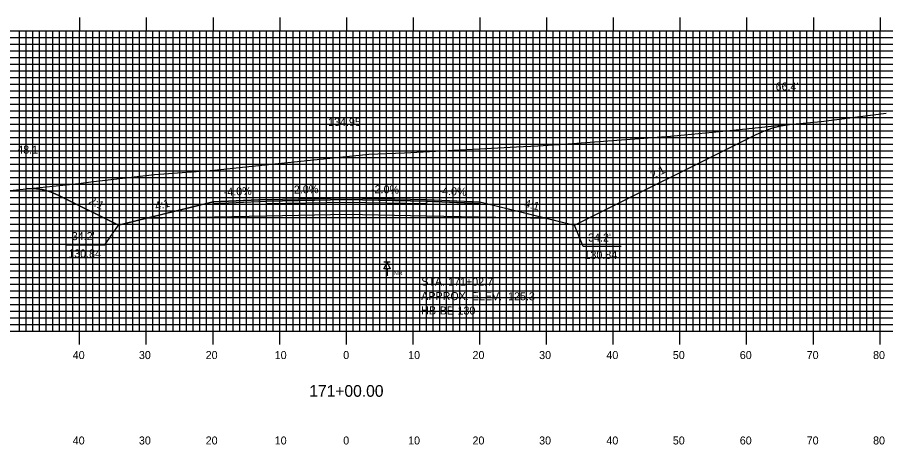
# Model space of a CAD drawing. Extents: x 1782647 to 1782990, y 442591 to 442811.
# Drawn here: x 1782763.6 to 1782893.8, y 442656.6 to 442720.7 of the extents above; entities that cross this region are included whole.
import ezdxf

# ---------------------------------------------------------------- set-up
doc = ezdxf.new("R2010")
doc.units = 0
for name, color, linetype in [('ANNOTATION', 7, 'Continuous'), ('BORING - NO REFUSAL', 7, 'Continuous'), ('D_Roadway_Centerline', 7, 'Continuous'), ('D_Roadway_Centerline_Text', 7, 'Continuous'), ('D_Roadway_Edge_Shoulder', 7, 'Continuous'), ('D_Roadway_Edge_TW', 7, 'Continuous'), ('D_Roadway_Pavement', 7, 'Continuous'), ('D_Roadway_SlopeLines', 7, 'Continuous'), ('D_Roadway_SubGrade', 7, 'Continuous'), ('D_Text_Standard', 7, 'Continuous'), ('H_V ANNOTATION', 7, 'Continuous'), ('MAJOR', 7, 'Continuous'), ('MINOR', 7, 'Continuous'), ('S_Roadway_Centerline', 7, 'Continuous')]:
    doc.layers.add(name, color=color, linetype=linetype)

msp = doc.modelspace()

# ---------------------------------------------------------------- linework, layer by layer
at = {"layer": 'ANNOTATION'}
for points in [[(1782771.04, 442686.57), (1782776.74, 442686.57), (1782778.77, 442689.51)], [(1782854.14, 442686.35), (1782848.45, 442686.35), (1782847.12, 442689.51)]]:
    msp.add_lwpolyline(points, dxfattribs=at)
at = {"layer": 'BORING - NO REFUSAL'}
for p, q in [((1782819.53, 442683.97), (1782818.57, 442683.97)), ((1782819.05, 442683.01), (1782819.05, 442681.95))]:
    msp.add_line(p, q, dxfattribs=at)
msp.add_lwpolyline([(1782819.05, 442683.97), (1782819.53, 442683.01), (1782818.57, 442683.01)], close=True, dxfattribs=at)
at = {"layer": 'D_Roadway_Centerline'}
msp.add_lwpolyline([(1782764.82, 442694.98), (1782766.07, 442695.02), (1782767.32, 442694.86), (1782768.57, 442694.52), (1782769.82, 442693.99), (1782778.77, 442689.51), (1782782.77, 442690.51), (1782792.95, 442693.05), (1782800.95, 442693.37), (1782812.95, 442693.61), (1782824.95, 442693.37), (1782832.95, 442693.05), (1782843.12, 442690.51), (1782847.12, 442689.51), (1782874.36, 442703.13), (1782875.61, 442703.69), (1782876.86, 442704.13), (1782878.11, 442704.44), (1782879.36, 442704.62)], dxfattribs=at)
at = {"layer": 'D_Roadway_Edge_Shoulder'}
for points in [[(1782800.95, 442693.37), (1782792.95, 442693.05), (1782792.95, 442692.8), (1782800.95, 442693.12)], [(1782824.95, 442693.37), (1782832.95, 442693.05), (1782832.95, 442692.8), (1782824.95, 442693.12)]]:
    msp.add_lwpolyline(points, close=True, dxfattribs=at)
at = {"layer": 'D_Roadway_Edge_TW'}
msp.add_lwpolyline([(1782800.95, 442693.12), (1782800.95, 442693.37), (1782812.95, 442693.61), (1782824.95, 442693.37), (1782824.95, 442693.12), (1782812.95, 442693.36)], close=True, dxfattribs=at)
at = {"layer": 'D_Roadway_Pavement'}
msp.add_lwpolyline([(1782800.95, 442692.71), (1782800.95, 442693.12), (1782812.95, 442693.36), (1782824.95, 442693.12), (1782824.95, 442692.71), (1782812.95, 442692.95)], close=True, dxfattribs=at)
at = {"layer": 'D_Roadway_SlopeLines'}
for points in [[(1782847.12, 442689.51), (1782874.36, 442703.13), (1782875.61, 442703.69), (1782876.86, 442704.13), (1782878.11, 442704.44), (1782879.36, 442704.62)], [(1782778.77, 442689.51), (1782769.82, 442693.99), (1782768.57, 442694.52), (1782767.32, 442694.86), (1782766.07, 442695.02), (1782764.82, 442694.98)], [(1782792.95, 442693.05), (1782778.77, 442689.51)], [(1782832.95, 442693.05), (1782847.12, 442689.51)]]:
    msp.add_lwpolyline(points, dxfattribs=at)
at = {"layer": 'D_Roadway_SubGrade'}
msp.add_lwpolyline([(1782800.95, 442690.87), (1782782.77, 442690.51), (1782792.95, 442693.05), (1782792.95, 442692.8), (1782800.95, 442693.12), (1782812.95, 442693.36), (1782824.95, 442693.12), (1782832.95, 442692.8), (1782832.95, 442693.05), (1782843.12, 442690.51), (1782824.95, 442690.87), (1782812.95, 442691.11)], close=True, dxfattribs=at)
at = {"layer": 'MAJOR'}
for p, q in [((1782772.95, 442720.67), (1782772.95, 442718.67)), ((1782782.95, 442720.67), (1782782.95, 442718.67)), ((1782792.95, 442720.67), (1782792.95, 442718.67)), ((1782802.95, 442720.67), (1782802.95, 442718.67)), ((1782812.95, 442720.67), (1782812.95, 442718.67)), ((1782822.95, 442720.67), (1782822.95, 442718.67)), ((1782832.95, 442720.67), (1782832.95, 442718.67)), ((1782842.95, 442720.67), (1782842.95, 442718.67)), ((1782852.95, 442720.67), (1782852.95, 442718.67)), ((1782862.95, 442720.67), (1782862.95, 442718.67)), ((1782872.95, 442720.67), (1782872.95, 442718.67)), ((1782882.95, 442720.67), (1782882.95, 442718.67)), ((1782892.95, 442720.67), (1782892.95, 442718.67)), ((1782672.95, 442718.67), (1782952.95, 442718.67)), ((1782672.95, 442718.67), (1782952.95, 442718.67)), ((1782772.95, 442673.67), (1782772.95, 442718.67)), ((1782782.95, 442673.67), (1782782.95, 442718.67)), ((1782792.95, 442673.67), (1782792.95, 442718.67)), ((1782802.95, 442673.67), (1782802.95, 442718.67)), ((1782812.95, 442673.67), (1782812.95, 442718.67)), ((1782822.95, 442673.67), (1782822.95, 442718.67)), ((1782832.95, 442673.67), (1782832.95, 442718.67)), ((1782842.95, 442673.67), (1782842.95, 442718.67)), ((1782852.95, 442673.67), (1782852.95, 442718.67)), ((1782862.95, 442673.67), (1782862.95, 442718.67)), ((1782872.95, 442673.67), (1782872.95, 442718.67)), ((1782882.95, 442673.67), (1782882.95, 442718.67)), ((1782892.95, 442673.67), (1782892.95, 442718.67)), ((1782672.95, 442713.67), (1782952.95, 442713.67)), ((1782672.95, 442708.67), (1782952.95, 442708.67)), ((1782672.95, 442703.67), (1782952.95, 442703.67)), ((1782672.95, 442698.67), (1782952.95, 442698.67)), ((1782672.95, 442693.67), (1782952.95, 442693.67)), ((1782672.95, 442688.67), (1782952.95, 442688.67)), ((1782672.95, 442683.67), (1782952.95, 442683.67)), ((1782672.95, 442678.67), (1782952.95, 442678.67)), ((1782672.95, 442673.67), (1782952.95, 442673.67)), ((1782672.95, 442673.67), (1782952.95, 442673.67)), ((1782772.95, 442671.66), (1782772.95, 442673.67)), ((1782782.95, 442671.66), (1782782.95, 442673.67)), ((1782792.95, 442671.66), (1782792.95, 442673.67)), ((1782802.95, 442671.66), (1782802.95, 442673.67)), ((1782812.95, 442671.66), (1782812.95, 442673.67)), ((1782822.95, 442671.66), (1782822.95, 442673.67)), ((1782832.95, 442671.66), (1782832.95, 442673.67)), ((1782842.95, 442671.66), (1782842.95, 442673.67)), ((1782852.95, 442671.66), (1782852.95, 442673.67)), ((1782862.95, 442671.66), (1782862.95, 442673.67)), ((1782872.95, 442671.66), (1782872.95, 442673.67)), ((1782882.95, 442671.66), (1782882.95, 442673.67)), ((1782892.95, 442671.66), (1782892.95, 442673.67))]:
    msp.add_line(p, q, dxfattribs=at)
at = {"layer": 'MINOR'}
for p, q in [((1782763.95, 442673.67), (1782763.95, 442718.67)), ((1782764.95, 442673.67), (1782764.95, 442718.67)), ((1782765.95, 442673.67), (1782765.95, 442718.67)), ((1782766.95, 442673.67), (1782766.95, 442718.67)), ((1782767.95, 442673.67), (1782767.95, 442718.67)), ((1782768.95, 442673.67), (1782768.95, 442718.67)), ((1782769.95, 442673.67), (1782769.95, 442718.67)), ((1782770.95, 442673.67), (1782770.95, 442718.67)), ((1782771.95, 442673.67), (1782771.95, 442718.67)), ((1782773.95, 442673.67), (1782773.95, 442718.67)), ((1782774.95, 442673.67), (1782774.95, 442718.67)), ((1782775.95, 442673.67), (1782775.95, 442718.67)), ((1782776.95, 442673.67), (1782776.95, 442718.67)), ((1782777.95, 442673.67), (1782777.95, 442718.67)), ((1782778.95, 442673.67), (1782778.95, 442718.67)), ((1782779.95, 442673.67), (1782779.95, 442718.67)), ((1782780.95, 442673.67), (1782780.95, 442718.67)), ((1782781.95, 442673.67), (1782781.95, 442718.67)), ((1782783.95, 442673.67), (1782783.95, 442718.67)), ((1782784.95, 442673.67), (1782784.95, 442718.67)), ((1782785.95, 442673.67), (1782785.95, 442718.67)), ((1782786.95, 442673.67), (1782786.95, 442718.67)), ((1782787.95, 442673.67), (1782787.95, 442718.67)), ((1782788.95, 442673.67), (1782788.95, 442718.67)), ((1782789.95, 442673.67), (1782789.95, 442718.67)), ((1782790.95, 442673.67), (1782790.95, 442718.67)), ((1782791.95, 442673.67), (1782791.95, 442718.67)), ((1782793.95, 442673.67), (1782793.95, 442718.67)), ((1782794.95, 442673.67), (1782794.95, 442718.67)), ((1782795.95, 442673.67), (1782795.95, 442718.67)), ((1782796.95, 442673.67), (1782796.95, 442718.67)), ((1782797.95, 442673.67), (1782797.95, 442718.67)), ((1782798.95, 442673.67), (1782798.95, 442718.67)), ((1782799.95, 442673.67), (1782799.95, 442718.67)), ((1782800.95, 442673.67), (1782800.95, 442718.67)), ((1782801.95, 442673.67), (1782801.95, 442718.67)), ((1782803.95, 442673.67), (1782803.95, 442718.67)), ((1782804.95, 442673.67), (1782804.95, 442718.67)), ((1782805.95, 442673.67), (1782805.95, 442718.67)), ((1782806.95, 442673.67), (1782806.95, 442718.67)), ((1782807.95, 442673.67), (1782807.95, 442718.67)), ((1782808.95, 442673.67), (1782808.95, 442718.67)), ((1782809.95, 442673.67), (1782809.95, 442718.67)), ((1782810.95, 442673.67), (1782810.95, 442718.67)), ((1782811.95, 442673.67), (1782811.95, 442718.67)), ((1782813.95, 442673.67), (1782813.95, 442718.67)), ((1782814.95, 442673.67), (1782814.95, 442718.67)), ((1782815.95, 442673.67), (1782815.95, 442718.67)), ((1782816.95, 442673.67), (1782816.95, 442718.67)), ((1782817.95, 442673.67), (1782817.95, 442718.67)), ((1782818.95, 442673.67), (1782818.95, 442718.67)), ((1782819.95, 442673.67), (1782819.95, 442718.67)), ((1782820.95, 442673.67), (1782820.95, 442718.67)), ((1782821.95, 442673.67), (1782821.95, 442718.67)), ((1782823.95, 442673.67), (1782823.95, 442718.67)), ((1782824.95, 442673.67), (1782824.95, 442718.67)), ((1782825.95, 442673.67), (1782825.95, 442718.67)), ((1782826.95, 442673.67), (1782826.95, 442718.67)), ((1782827.95, 442673.67), (1782827.95, 442718.67)), ((1782828.95, 442673.67), (1782828.95, 442718.67)), ((1782829.95, 442673.67), (1782829.95, 442718.67)), ((1782830.95, 442673.67), (1782830.95, 442718.67)), ((1782831.95, 442673.67), (1782831.95, 442718.67)), ((1782833.95, 442673.67), (1782833.95, 442718.67)), ((1782834.95, 442673.67), (1782834.95, 442718.67)), ((1782835.95, 442673.67), (1782835.95, 442718.67)), ((1782836.95, 442673.67), (1782836.95, 442718.67)), ((1782837.95, 442673.67), (1782837.95, 442718.67)), ((1782838.95, 442673.67), (1782838.95, 442718.67)), ((1782839.95, 442673.67), (1782839.95, 442718.67)), ((1782840.95, 442673.67), (1782840.95, 442718.67)), ((1782841.95, 442673.67), (1782841.95, 442718.67)), ((1782843.95, 442673.67), (1782843.95, 442718.67)), ((1782844.95, 442673.67), (1782844.95, 442718.67)), ((1782845.95, 442673.67), (1782845.95, 442718.67)), ((1782846.95, 442673.67), (1782846.95, 442718.67)), ((1782847.95, 442673.67), (1782847.95, 442718.67)), ((1782848.95, 442673.67), (1782848.95, 442718.67)), ((1782849.95, 442673.67), (1782849.95, 442718.67)), ((1782850.95, 442673.67), (1782850.95, 442718.67)), ((1782851.95, 442673.67), (1782851.95, 442718.67)), ((1782853.95, 442673.67), (1782853.95, 442718.67)), ((1782854.95, 442673.67), (1782854.95, 442718.67)), ((1782855.95, 442673.67), (1782855.95, 442718.67)), ((1782856.95, 442673.67), (1782856.95, 442718.67)), ((1782857.95, 442673.67), (1782857.95, 442718.67)), ((1782858.95, 442673.67), (1782858.95, 442718.67)), ((1782859.95, 442673.67), (1782859.95, 442718.67)), ((1782860.95, 442673.67), (1782860.95, 442718.67)), ((1782861.95, 442673.67), (1782861.95, 442718.67)), ((1782863.95, 442673.67), (1782863.95, 442718.67)), ((1782864.95, 442673.67), (1782864.95, 442718.67)), ((1782865.95, 442673.67), (1782865.95, 442718.67)), ((1782866.95, 442673.67), (1782866.95, 442718.67)), ((1782867.95, 442673.67), (1782867.95, 442718.67)), ((1782868.95, 442673.67), (1782868.95, 442718.67)), ((1782869.95, 442673.67), (1782869.95, 442718.67)), ((1782870.95, 442673.67), (1782870.95, 442718.67)), ((1782871.95, 442673.67), (1782871.95, 442718.67)), ((1782873.95, 442673.67), (1782873.95, 442718.67)), ((1782874.95, 442673.67), (1782874.95, 442718.67)), ((1782875.95, 442673.67), (1782875.95, 442718.67)), ((1782876.95, 442673.67), (1782876.95, 442718.67)), ((1782877.95, 442673.67), (1782877.95, 442718.67)), ((1782878.95, 442673.67), (1782878.95, 442718.67)), ((1782879.95, 442673.67), (1782879.95, 442718.67)), ((1782880.95, 442673.67), (1782880.95, 442718.67)), ((1782881.95, 442673.67), (1782881.95, 442718.67)), ((1782883.95, 442673.67), (1782883.95, 442718.67)), ((1782884.95, 442673.67), (1782884.95, 442718.67)), ((1782885.95, 442673.67), (1782885.95, 442718.67)), ((1782886.95, 442673.67), (1782886.95, 442718.67)), ((1782887.95, 442673.67), (1782887.95, 442718.67)), ((1782888.95, 442673.67), (1782888.95, 442718.67)), ((1782889.95, 442673.67), (1782889.95, 442718.67)), ((1782890.95, 442673.67), (1782890.95, 442718.67)), ((1782891.95, 442673.67), (1782891.95, 442718.67)), ((1782672.95, 442717.67), (1782952.95, 442717.67)), ((1782672.95, 442716.67), (1782952.95, 442716.67)), ((1782672.95, 442715.67), (1782952.95, 442715.67)), ((1782672.95, 442714.67), (1782952.95, 442714.67)), ((1782672.95, 442712.67), (1782952.95, 442712.67)), ((1782672.95, 442711.67), (1782952.95, 442711.67)), ((1782672.95, 442710.67), (1782952.95, 442710.67)), ((1782672.95, 442709.67), (1782952.95, 442709.67)), ((1782672.95, 442707.67), (1782952.95, 442707.67)), ((1782672.95, 442706.67), (1782952.95, 442706.67)), ((1782672.95, 442705.67), (1782952.95, 442705.67)), ((1782672.95, 442704.67), (1782952.95, 442704.67)), ((1782672.95, 442702.67), (1782952.95, 442702.67)), ((1782672.95, 442701.67), (1782952.95, 442701.67)), ((1782672.95, 442700.67), (1782952.95, 442700.67)), ((1782672.95, 442699.67), (1782952.95, 442699.67)), ((1782672.95, 442697.67), (1782952.95, 442697.67)), ((1782672.95, 442696.67), (1782952.95, 442696.67)), ((1782672.95, 442695.67), (1782952.95, 442695.67)), ((1782672.95, 442694.67), (1782952.95, 442694.67)), ((1782672.95, 442692.67), (1782952.95, 442692.67)), ((1782672.95, 442691.67), (1782952.95, 442691.67)), ((1782672.95, 442690.67), (1782952.95, 442690.67)), ((1782672.95, 442689.67), (1782952.95, 442689.67)), ((1782672.95, 442687.67), (1782952.95, 442687.67)), ((1782672.95, 442686.67), (1782952.95, 442686.67)), ((1782672.95, 442685.67), (1782952.95, 442685.67)), ((1782672.95, 442684.67), (1782952.95, 442684.67)), ((1782672.95, 442682.67), (1782952.95, 442682.67)), ((1782672.95, 442681.67), (1782952.95, 442681.67)), ((1782672.95, 442680.67), (1782952.95, 442680.67)), ((1782672.95, 442679.67), (1782952.95, 442679.67)), ((1782672.95, 442677.67), (1782952.95, 442677.67)), ((1782672.95, 442676.67), (1782952.95, 442676.67)), ((1782672.95, 442675.67), (1782952.95, 442675.67)), ((1782672.95, 442674.67), (1782952.95, 442674.67))]:
    msp.add_line(p, q, dxfattribs=at)
at = {"layer": 'S_Roadway_Centerline'}
msp.add_lwpolyline([(1782751.06, 442693.59), (1782771.92, 442695.7), (1782773.18, 442695.83), (1782774.63, 442696.01), (1782784.19, 442697.13), (1782793.15, 442697.75), (1782797.37, 442698.22), (1782816.32, 442700.19), (1782821.67, 442700.38), (1782838.46, 442701.28), (1782841.62, 442701.44), (1782844.8, 442701.62), (1782861.52, 442702.86), (1782869.94, 442703.67), (1782877.1, 442704.4), (1782884.1, 442705.09), (1782893.86, 442706.3)], dxfattribs=at)

# ---------------------------------------------------------------- texts
at = {"layer": 'ANNOTATION'}
for s, rotation, p in [('2:1', 26.5651, (1782858.88, 442696.43)), ('-4.0%', 2.2906, (1782794.58, 442693.92)), ('-2.0%', 1.1458, (1782804.55, 442694.25)), ('-2.0%', 358.8542, (1782816.63, 442694.34)), ('-4.0%', 357.7094, (1782826.74, 442694.1)), ('2:1', 333.4349, (1782774.23, 442692.82)), ('4:1', 14.0362, (1782784.4, 442691.78)), ('4:1', 345.9638, (1782839.54, 442692.27))]:
    msp.add_text(s, height=1.2, rotation=rotation, dxfattribs=at).set_placement(p)
for s, p in [("34.2'", (1782771.78, 442687.29)), ("34.2'", (1782849.18, 442687.08)), ('130.84', (1782771.24, 442684.69)), ('130.84', (1782848.64, 442684.48))]:
    msp.add_text(s, height=1.2, dxfattribs=at).set_placement(p)
at = {"layer": 'BORING - NO REFUSAL'}
msp.add_text('NR', height=0.7, dxfattribs=at).set_placement((1782819.98, 442682.05))
for s, p in [('STA. 171+02.7', (1782824.17, 442680.48)), ('APPROX. ELEV.  125.3', (1782824.16, 442678.32)), ('HB-BE-130', (1782824.16, 442676.16))]:
    msp.add_text(s, height=1.2, rotation=359.8142, dxfattribs=at).set_placement(p)
at = {"layer": 'D_Roadway_Centerline'}
for s, p in [('C', (1782812.94, 442693.61)), ('L', (1782812.95, 442693.61))]:
    msp.add_text(s, height=0.0146, dxfattribs=at).set_placement(p)
at = {"layer": 'D_Roadway_Centerline_Text'}
msp.add_text('134.95', height=1.2, dxfattribs=at).set_placement((1782810.2, 442704.4))
at = {"layer": 'D_Text_Standard'}
for s, p in [("66.4'", (1782877.29, 442709.71)), ("48.1'", (1782763.6, 442700.26))]:
    msp.add_text(s, height=1.2, dxfattribs=at).set_placement(p)
at = {"layer": 'H_V ANNOTATION'}
for s, height, p in [('40', 1.2, (1782771.92, 442669.47)), ('30', 1.2, (1782781.84, 442669.47)), ('20', 1.2, (1782791.85, 442669.47)), ('10', 1.2, (1782802.2, 442669.47)), ('0', 1.2, (1782812.47, 442669.47)), ('10', 1.2, (1782822.2, 442669.47)), ('20', 1.2, (1782831.85, 442669.47)), ('30', 1.2, (1782841.84, 442669.47)), ('40', 1.2, (1782851.92, 442669.47)), ('50', 1.2, (1782861.88, 442669.47)), ('60', 1.2, (1782871.92, 442669.47)), ('70', 1.2, (1782881.95, 442669.47)), ('80', 1.2, (1782891.9, 442669.47)), ('171+00.00', 1.75, (1782807.38, 442663.82)), ('40', 1.2, (1782771.92, 442656.67)), ('30', 1.2, (1782781.84, 442656.67)), ('20', 1.2, (1782791.85, 442656.67)), ('10', 1.2, (1782802.2, 442656.67)), ('0', 1.2, (1782812.47, 442656.67)), ('10', 1.2, (1782822.2, 442656.67)), ('20', 1.2, (1782831.85, 442656.67)), ('30', 1.2, (1782841.84, 442656.67)), ('40', 1.2, (1782851.92, 442656.67)), ('50', 1.2, (1782861.88, 442656.67)), ('60', 1.2, (1782871.92, 442656.67)), ('70', 1.2, (1782881.95, 442656.67)), ('80', 1.2, (1782891.9, 442656.67))]:
    msp.add_text(s, height=height, dxfattribs=at).set_placement(p)

doc.saveas('drawing.dxf')
